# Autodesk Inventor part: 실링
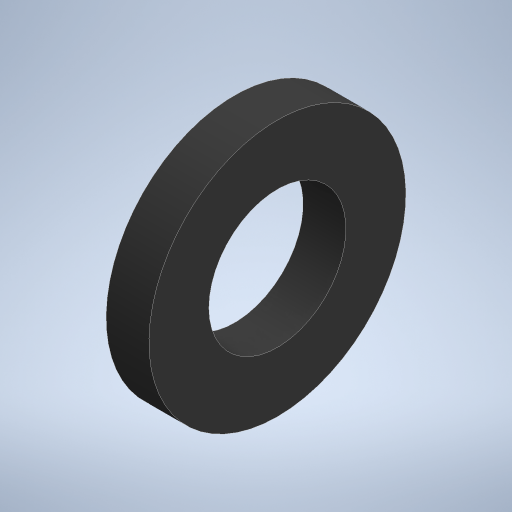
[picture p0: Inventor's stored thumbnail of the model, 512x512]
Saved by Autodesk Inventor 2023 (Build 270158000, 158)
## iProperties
Created: 2026-03
Part Number: 실링
Material: 고무, 실리콘
Document SubType Name: Modeling
Designer: home
Density: 1.25 g/cm^3
Appearance: 기본값
Author: jhkim
Sending System: Autodesk Inventor 2026
Preprocessor: ST-DEVELOPER v20.1
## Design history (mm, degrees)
feature "솔리드1"
node "솔리드2"
